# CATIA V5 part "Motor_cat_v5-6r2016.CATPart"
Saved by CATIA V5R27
Part number: Motor
Bounding box of the stored display mesh (mm): x -60 to 60, y -28 to 67, z -67.5 to 60
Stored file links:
  E:\_Deepak\2017_Deepak\CATIA\Resources\Tutorial Files\Tutorials\c12_catia_v5_6r2015_tut\c12Tut1\Motor_cat_v5-6r2016.CATPart
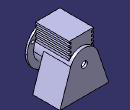
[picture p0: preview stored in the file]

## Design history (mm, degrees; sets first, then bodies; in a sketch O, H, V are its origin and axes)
Body1 (main body)
  Sketch1 on zx-plane, origin (0, 0, 0), H (-1, 0, 0), V (0, 0, 1)
    arc A1 centre (0, 0) radius 35 from (33.1265, 11.2976) to (-33.1265, 11.2976) ccw
    line L1 (-60, -67.5) -> (60, -67.5)
    point P1 (-60, -67.5)
    line L2 (60, -67.5) -> (33.1265, 11.2976)
    line L3 (-60, -67.5) -> (-33.1265, 11.2976)
    point P4 (-33.1265, 11.2976)
    point P5 (-33.1265, 11.2976)
    radius A1 = 35
    length L1 = 120
    distance H L1 = 67.5
    distance P1 V = 60
    horizontal: L1 H
    tangency: L3 A1, L2 A1
    coincidence: L3 P5, P4 A1, P4 P5
  Pad1: profile Sketch1, direction (0, 1, 0), length 67
  Sketch2 on face of Pad1, origin (0, 67, 0), H (-1, 0, 0), V (0, 0, 1)
    circle A1 centre (0, 0) radius 35
    reference projected arc E1 centre (0, 0) radius 35 from (33.1265, 11.2976) to (-33.1265, 11.2976) ccw from edge [face of Pad1 from Sketch1.A1 | end face of Pad1]
    reference projected arc E2 centre (0, 0) radius 35 from (33.1265, 11.2976) to (-33.1265, 11.2976) ccw from edge [face of Pad1 from Sketch1.A1 | end face of Pad1]
    coincidence: A1 E1
    concentricity: A1 E2
  Pad2: profile Sketch2, direction (0, -1, 0), length 90
  Sketch3 on xy-plane, origin (0, 0, 0), H (1, 0, 0), V (0, 1, 0)
    line L1 (-30, 59.5) -> (30, 59.5)
    line L2 (30, 59.5) -> (30, -23)
    line L3 (30, -23) -> (-30, -23)
    line L4 (-30, -23) -> (-30, 59.5)
    reference projected line E1 (-35, -23) -> (35, -23) from edge of Pad2
    reference projected line E2 (33.1265, 67) -> (-33.1265, 67) from edge of Pad1
    length L1 = 60
    distance L4 V = 30
    distance E2 L1 = 7.5
    horizontal: L1 H, L3 H
    vertical: L2 V, L4 V
    coincidence: E1 L3
  Pad3: profile Sketch3, direction (0, 0, 1), length 60
  Sketch4 on face of Pad2, origin (0, -23, 0), H (1, 0, 0), V (0, 0, 1)
    circle A1 centre (0, 0) radius 50
    radius A1 = 50
  Pad4: profile Sketch4, direction (0, -1, 0), length 5
  Sketch5 on face of Pad3, origin (0, 59.5, 0), H (-1, 0, 0), V (0, 0, 1)
    line L1 (-30, 28.8) -> (-25, 28.8)
    line L2 (-25, 28.8) -> (-25, 24.3)
    line L3 (-25, 24.3) -> (-30, 24.3)
    line L4 (-30, 24.3) -> (-30, 28.8)
    reference projected line E1 (-30, 0) -> (-30, 60) from edge of Pad3
    length L1 = 5
    length L2 = 4.5
    distance L3 H = 24.3
    horizontal: L1 H, L3 H
    vertical: L2 V, L4 V
    coincidence: L4 E1
  Pocket1: profile Sketch5, direction (0, -1, 0), up to face of Pad3
  RectPattern1: of Pocket1, direction 1 instances 4, spacing 9, along edge of Pad3 reversed, direction 2 instances 2, spacing 55, along edge of Pad3
  Sketch6 on face of Pad4, origin (0, -28, 0), H (1, 0, 0), V (0, 0, 1)
    circle A1 centre (0, -42.5) radius 3.75
    point P1 (0, -42.5)
    radius A1 = 3.75
    distance P1 H = 42.5
    coincidence: P1 V
  Pocket2: profile Sketch6, direction (0, 1, 0), length 12.7
  CircPattern1: of Pocket2, instances 3, angular step 120, axis from face
  Sketch7 on face of Pad4, origin (0, -28, 0), H (1, 0, 0), V (0, 0, 1)
    circle A1 centre (0, 0) radius 30
    circle A2 centre (0, 0) radius 7.5
    radius A1 = 30
    radius A2 = 7.5
  MultiPocket1: profile Sketch7, domains (length 254; length 90)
